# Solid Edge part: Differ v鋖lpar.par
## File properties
Author: Türk
Template: Iso Part.par
Last saved by: Türk
Revision: 19
Application: Solid Edge
Accuracy: 0,990
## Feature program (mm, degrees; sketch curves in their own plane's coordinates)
pattern "PatternOccurrence_1"  XOffset = 32.7273 deg
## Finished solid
Body 1: solid body, 113 faces, 293 edges, 182 vertices.
  Faces by surface: spline 55, plane 38, cone 11, cylinder 9
  Edges by curve: curve on surface 110, line 100, circle 61, spline 22
Bounding box of the edges (mm; curved faces can reach further): 64.000 x 232.500 x 64.000, from (-32, -12.5, -32) to (32, 220, 32).
Cylindrical faces by radius (mm): R7.5 x2, R10 x4, R25 x1, R27.5 x1, R32 x1
Conical faces (half-angle, radius in mm at the cone's reference point): 45 deg R30 x11
Planar faces by outward normal: +x 2, +y 14, +z 2, -x 2, -y 14, -z 2, oblique 2
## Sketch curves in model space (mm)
line (-27.5, 170, -27.5) -> (-27.5, 170, 27.5)
line (-27.5, 170, 27.5) -> (27.5, 170, 27.5)
line (27.5, 170, 27.5) -> (27.5, 170, -27.5)
line (27.5, 170, -27.5) -> (-27.5, 170, -27.5)
line (-27.5, 220, 0) -> (-27.5, 205, 0)
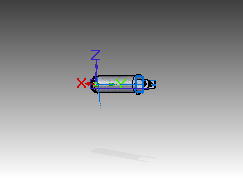
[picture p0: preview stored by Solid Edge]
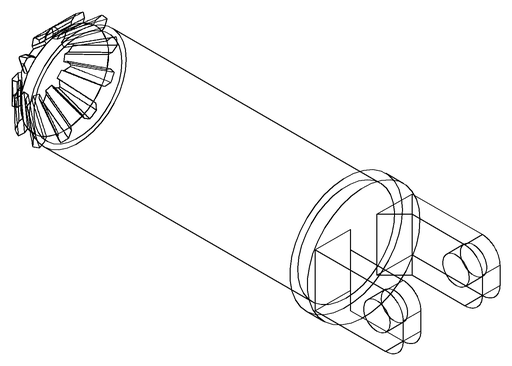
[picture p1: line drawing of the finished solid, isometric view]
